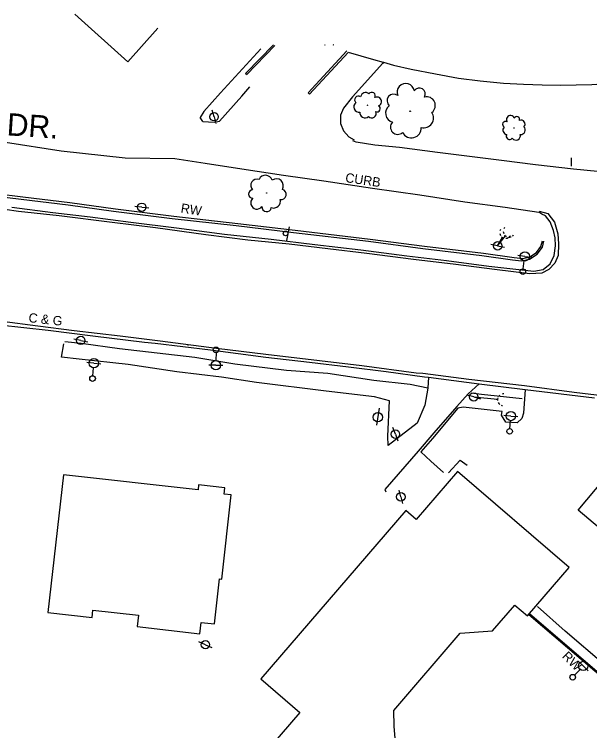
# Model space of a CAD drawing. Extents: x 1722896 to 1754269, y 648279 to 666297.
# Drawn here: x 1726198.2 to 1726506.8, y 658280.2 to 658664.3 of the extents above; entities that cross this region are included whole.
import ezdxf

# ---------------------------------------------------------------- set-up
doc = ezdxf.new("R2010")
doc.units = 0
for name, color, linetype in [('DESIGN - CENTERLINE - Proposed Text', 7, 'Continuous'), ('DESIGN - PUBLIC HEARING - Shapes', 7, 'Continuous'), ('DESIGN - SCRATCH - User 1', 7, 'Continuous'), ('DESIGN - SHEET - Linework', 7, 'Continuous'), ('SURVEY - CENTERLINE - Preliminary Text', 7, 'Continuous'), ('SURVEY - CONTROL with Text', 7, 'Continuous'), ('SURVEY - DTM - Breaklines', 7, 'Continuous'), ('SURVEY - VEGETATION - Features with Text', 7, 'Continuous')]:
    doc.layers.add(name, color=color, linetype=linetype)

msp = doc.modelspace()

# ---------------------------------------------------------------- linework, layer by layer
at = {"layer": 'DESIGN - CENTERLINE - Proposed Text'}
for points in [[(1726230.57, 658664.33), (1726259.14, 658638.87), (1726275.15, 658656.84)], [(1726337.85, 658647.56), (1726322.72, 658631.96), (1726322.33, 658632.71), (1726337.16, 658648.05)], [(1726337.85, 658647.57), (1726337.85, 658647.56)], [(1726364.73, 658647.87), (1726364.79, 658647.92)], [(1726364.79, 658647.92), (1726364.73, 658647.87)], [(1726369.16, 658647.99), (1726369.37, 658647.87)], [(1726369.37, 658647.87), (1726369.31, 658647.93), (1726369.17, 658647.99)], [(1726396.21, 658638.61), (1726401.6, 658637.15), (1726411.07, 658634.99), (1726424.17, 658632.36), (1726436.48, 658630.05), (1726448.04, 658628.66), (1726460.65, 658627.43), (1726471.31, 658626.86), (1726481.34, 658626.43), (1726491.25, 658626.31), (1726507.93, 658626.63), (1726521.3, 658627.67), (1726536.89, 658629.14), (1726548.71, 658630.74), (1726564.84, 658633.77), (1726582.8, 658638.11), (1726595.63, 658641.64), (1726615.41, 658647.76), (1726616.16, 658648.07)], [(1726377.24, 658643.79), (1726356.56, 658621.6), (1726355.76, 658622.3), (1726376.54, 658644.72)], [(1726377.18, 658643.89), (1726377.24, 658643.79)], [(1726377.24, 658644.02), (1726390.77, 658640.08), (1726396.05, 658638.65)], [(1726395.92, 658638.07), (1726379.54, 658620.09), (1726374.67, 658614.04), (1726373.12, 658610.27), (1726373.17, 658605.77), (1726374.74, 658601.83), (1726377.67, 658598.55), (1726380.51, 658597.01), (1726380.55, 658597.11)], [(1726396.19, 658638.37), (1726395.92, 658638.07)], [(1726396.04, 658637.96), (1726396.19, 658638.37)], [(1726496.83, 658587.41), (1726496.94, 658582.94)], [(1726474.26, 658342.49), (1726530.29, 658294.5)], [(1726474.72, 658342.86), (1726530.75, 658294.88)]]:
    msp.add_lwpolyline(points, dxfattribs=at)
for points in [[(1726523.04, 658425.07), (1726583.75, 658373.94), (1726561.29, 658347.28), (1726500.59, 658398.41)], [(1726408.14, 658398.26), (1726330.47, 658307.89), (1726351.36, 658289.94), (1726335.79, 658271.83), (1726356.07, 658254.4), (1726349.83, 658247.15), (1726384.69, 658217.19), (1726388.63, 658221.78), (1726412.46, 658201.3), (1726430.77, 658222.61), (1726390.38, 658257.32), (1726402.8, 658271.77), (1726401.96, 658282.67), (1726401.75, 658290.96), (1726437.26, 658332.38), (1726454.63, 658333.78), (1726466.71, 658347.52), (1726473.45, 658341.72), (1726495.78, 658367.7), (1726435.87, 658419.19), (1726413.75, 658393.44)], [(1726224.49, 658417.45), (1726216.19, 658343.59), (1726239.92, 658340.93), (1726240.36, 658344.81), (1726264.82, 658342.06), (1726264.13, 658335.97), (1726297.75, 658332.19), (1726298.42, 658338.23), (1726305.5, 658337.43), (1726308.22, 658361.65), (1726309.49, 658361.51), (1726314.55, 658406.56), (1726310.74, 658406.99), (1726311.12, 658410.4), (1726297.06, 658411.98), (1726296.77, 658409.34)]]:
    msp.add_lwpolyline(points, close=True, dxfattribs=at)
at = {"layer": 'DESIGN - PUBLIC HEARING - Shapes'}
for p, q in [((1726345.63, 658550.34), (1726344.23, 658542.97)), ((1726392.7, 658444.07), (1726394.03, 658453.1)), ((1726393.16, 658448.26), (1726393.16, 658448.26))]:
    msp.add_line(p, q, dxfattribs=at)
for centre, radius in [((1726343.72, 658546.87), 1.25), ((1726393.17, 658448.28), 2.5)]:
    msp.add_circle(centre, radius, dxfattribs=at)
at = {"layer": 'DESIGN - SCRATCH - User 1'}
for points in [[(1726094.96, 658584.83), (1726116.03, 658578.35), (1726126.54, 658574.84), (1726156.53, 658570.93), (1726187.07, 658566.98), (1726201.87, 658565.19), (1726227.04, 658562.14), (1726251.44, 658558.82), (1726282.92, 658554.87), (1726317.23, 658551.02), (1726347.94, 658547.3), (1726388.24, 658542.61), (1726417.33, 658538.77), (1726448.9, 658535.04), (1726465.48, 658532.74), (1726470.32, 658532.16), (1726474.61, 658533.09), (1726478.63, 658535.74), (1726481.43, 658539.41), (1726482.31, 658542.68)], [(1726096.14, 658585.96), (1726117.24, 658579.48), (1726127.63, 658576.01), (1726157.47, 658572.12), (1726187.99, 658568.17), (1726202.78, 658566.38), (1726227.97, 658563.33), (1726252.37, 658560.01), (1726283.82, 658556.06), (1726318.13, 658552.21), (1726348.84, 658548.5), (1726389.14, 658543.8), (1726418.23, 658539.96), (1726449.8, 658536.23), (1726466.38, 658533.94), (1726470.95, 658533.38), (1726474.72, 658534.21), (1726478.26, 658536.58), (1726480.7, 658539.81), (1726481.5, 658542.79)]]:
    msp.add_lwpolyline(points, dxfattribs=at)
at = {"layer": 'SURVEY - CENTERLINE - Preliminary Text'}
for points in [[(1726330.47, 658645.83), (1726308.71, 658622.18), (1726299.77, 658612.28), (1726297.83, 658609)], [(1726299.3, 658606.94), (1726305.36, 658606.54), (1726308.29, 658607.08), (1726320.14, 658620.52), (1726324.54, 658625.39)], [(1726299.3, 658606.94), (1726297.83, 658609)], [(1726132.12, 658602.07), (1726161.34, 658597.9), (1726193.47, 658595.74), (1726223.25, 658591.16), (1726257.64, 658587.45), (1726284.24, 658586.95)], [(1726440.85, 658588.26), (1726425.11, 658590.26), (1726404.74, 658592.83), (1726391.48, 658594.25), (1726381.56, 658595.78), (1726379.79, 658596.43)], [(1726658.59, 658594.61), (1726655.67, 658591.17), (1726650.24, 658587.65), (1726639.85, 658584.85), (1726626.48, 658582.26), (1726605.57, 658580.12), (1726586.6, 658578.61), (1726566.07, 658577.96), (1726555.1, 658577.83), (1726537.4, 658578.67), (1726518.29, 658579.28), (1726498.14, 658581.3), (1726477.79, 658583.7), (1726459.58, 658585.94), (1726440.85, 658588.26)], [(1726284.24, 658586.95), (1726300.53, 658584.46), (1726320.18, 658581.45), (1726342.56, 658578.13), (1726364.14, 658575.07), (1726390.25, 658571.04), (1726415.77, 658567.51), (1726439.89, 658563.83), (1726461.5, 658560.85), (1726479.59, 658558.3)], [(1726479.78, 658558.79), (1726484.36, 658557.59), (1726487.92, 658552.8), (1726489.82, 658546.63), (1726490.1, 658541.19), (1726489.9, 658534.92), (1726488.19, 658530.86), (1726484.96, 658527.44), (1726481.21, 658525.51), (1726474.67, 658525.2), (1726455.76, 658527.48), (1726435.08, 658530.09), (1726412.37, 658532.84), (1726387.32, 658535.98), (1726366.39, 658538.57), (1726345.58, 658541.09), (1726323.49, 658543.26), (1726300.85, 658546.05), (1726273.87, 658549.75), (1726250.71, 658552.72), (1726222.29, 658556.2), (1726200.43, 658558.54), (1726178.21, 658561.73)], [(1726196.75, 658560.97), (1726218.77, 658558.14), (1726238.82, 658555.72), (1726260.74, 658552.89), (1726285.24, 658549.81), (1726310.96, 658546.46), (1726336.02, 658543.73), (1726359.45, 658540.89), (1726384, 658538.01), (1726408.72, 658534.78), (1726430.05, 658532.24), (1726452.7, 658529.35), (1726468.89, 658527.47), (1726476.79, 658526.67), (1726481.93, 658527.54), (1726485.64, 658530.46), (1726487.69, 658534.92), (1726488.49, 658540.16), (1726488.23, 658544.42), (1726487.39, 658548.45), (1726485.67, 658553.1), (1726483.05, 658556.24), (1726481.08, 658557.1), (1726479.59, 658558.3)], [(1726171.71, 658500.11), (1726189.99, 658497.9), (1726216.26, 658494.91), (1726240.28, 658491.94), (1726267.98, 658488.53), (1726273.76, 658487.92)], [(1726191.6, 658499.71), (1726210.82, 658497.21), (1726230.2, 658494.74), (1726254.9, 658491.93), (1726276.37, 658489.23), (1726306.66, 658485.28), (1726333.07, 658482.01), (1726361.89, 658478.71), (1726384.62, 658475.92), (1726413.82, 658472.11), (1726417.36, 658471.95), (1726441.94, 658468.68), (1726471.88, 658465.31), (1726498.58, 658461.68), (1726514.88, 658459.74)], [(1726419.92, 658463.8), (1726410.61, 658465.78), (1726391.04, 658468.01), (1726366.38, 658471.63), (1726344.17, 658473.39), (1726316.44, 658476.74), (1726295.04, 658480.32), (1726254.64, 658484.92), (1726233.99, 658487.72), (1726225.32, 658488.7)], [(1726273.76, 658487.92), (1726303.35, 658484.33), (1726333.04, 658480.53), (1726356.54, 658477.82), (1726377.37, 658475.26), (1726397.63, 658472.73), (1726418.26, 658469.98), (1726420.34, 658469.71)], [(1726398.75, 658433.19), (1726398.49, 658438.03), (1726399.51, 658457.08), (1726391.33, 658459.18), (1726365.38, 658462.33), (1726328.16, 658466.94), (1726309.25, 658469.71), (1726285.34, 658472.55), (1726259.33, 658476.61), (1726232.99, 658479.35), (1726223.46, 658480.53), (1726224.79, 658487.7)], [(1726291.24, 658486.88), (1726291.17, 658486.82)], [(1726420.34, 658469.71), (1726419.92, 658463.8), (1726418.44, 658454.69), (1726414.21, 658445.08), (1726398.75, 658433.19)], [(1726420.34, 658469.71), (1726447.46, 658466.17), (1726472.28, 658463.15)], [(1726447.46, 658466.17), (1726441.72, 658460.82), (1726435.55, 658454.07)], [(1726472.28, 658463.15), (1726471.4, 658450.45), (1726470.42, 658447.67), (1726467.84, 658445.19), (1726461.89, 658445.62), (1726459.45, 658449.44), (1726459.82, 658451.26), (1726439.03, 658453.71), (1726436.06, 658453.1), (1726422.44, 658436.85), (1726416.21, 658429.66), (1726421.68, 658424.62), (1726428.46, 658418.58)], [(1726470.57, 658458.08), (1726448.87, 658460.47), (1726443.17, 658461.15)], [(1726472.28, 658463.15), (1726509.37, 658458.75)], [(1726435.55, 658454.07), (1726423.16, 658439.87), (1726414.87, 658430.09), (1726396.91, 658409.43), (1726397.42, 658408.21)], [(1726431.15, 658418.39), (1726437.36, 658425.21), (1726441.09, 658422.53)], [(1726546.23, 658306.6), (1726542.46, 658309.64), (1726540.53, 658308.38), (1726533.55, 658299.88), (1726514.62, 658315.72), (1726493.62, 658333.52), (1726478.81, 658346.85)]]:
    msp.add_lwpolyline(points, dxfattribs=at)
at = {"layer": 'SURVEY - DTM - Breaklines'}
for p, q in [((1726305.34, 658609.38), (1726304.38, 658613)), ((1726305.34, 658609.38), (1726306.31, 658605.76)), ((1726266.51, 658560.86), (1726262.77, 658561.19)), ((1726266.51, 658560.86), (1726270.24, 658560.53)), ((1726457.46, 658540.19), (1726461.66, 658545.56)), ((1726461.23, 658545.01), (1726461.66, 658545.56)), ((1726457.46, 658540.19), (1726460.12, 658544.65)), ((1726459.77, 658544.05), (1726460.12, 658544.65)), ((1726457.46, 658540.19), (1726453.76, 658540.85)), ((1726457.46, 658540.19), (1726461.15, 658539.54)), ((1726472.05, 658534.54), (1726468.33, 658535.03)), ((1726472.05, 658534.54), (1726475.77, 658534.05)), ((1726471.17, 658527.85), (1726471.72, 658532.06)), ((1726233.83, 658489.46), (1726230.15, 658490.14)), ((1726233.83, 658489.46), (1726237.52, 658488.78)), ((1726306.37, 658482.91), (1726306.32, 658478.66)), ((1726240.86, 658477.23), (1726237.13, 658477.56)), ((1726240.86, 658477.23), (1726244.6, 658476.9)), ((1726240.27, 658470.51), (1726240.64, 658474.74)), ((1726306.29, 658476.16), (1726302.54, 658476.21)), ((1726306.29, 658476.16), (1726310.04, 658476.11)), ((1726444.62, 658459.15), (1726441, 658460.12)), ((1726444.62, 658459.15), (1726448.25, 658458.17)), ((1726444.62, 658459.15), (1726457.36, 658457.91)), ((1726456.66, 658457.97), (1726457.36, 658457.91)), ((1726464.56, 658448.92), (1726460.83, 658449.23)), ((1726464, 658442.19), (1726464.36, 658446.42)), ((1726464.56, 658448.92), (1726468.3, 658448.61)), ((1726402.6, 658439.19), (1726401.28, 658442.7)), ((1726402.6, 658439.19), (1726403.91, 658435.68)), ((1726405.51, 658405.59), (1726404.54, 658409.21)), ((1726405.51, 658405.59), (1726406.48, 658401.97)), ((1726300.67, 658326.29), (1726297.22, 658327.76)), ((1726300.67, 658326.29), (1726304.12, 658324.81)), ((1726503.35, 658314.87), (1726500.61, 658317.43)), ((1726498.74, 658309.93), (1726501.64, 658313.04)), ((1726503.35, 658314.87), (1726506.09, 658312.31))]:
    msp.add_line(p, q, dxfattribs=at)
for centre, radius in [((1726305.34, 658609.38), 2.25), ((1726266.51, 658560.86), 2.25), ((1726457.46, 658540.19), 2.25), ((1726472.05, 658534.54), 2.5), ((1726470.97, 658526.36), 1.5), ((1726233.83, 658489.46), 2.25), ((1726306.39, 658484.41), 1.5), ((1726240.86, 658477.23), 2.5), ((1726306.29, 658476.16), 2.5), ((1726240.13, 658469.01), 1.5), ((1726444.62, 658459.15), 2.25), ((1726464.56, 658448.92), 2.5), ((1726463.88, 658440.69), 1.5), ((1726402.6, 658439.19), 2.25), ((1726405.51, 658405.59), 2.25), ((1726300.67, 658326.29), 2.25), ((1726503.35, 658314.87), 2.5), ((1726497.72, 658308.84), 1.5)]:
    msp.add_circle(centre, radius, dxfattribs=at)
for centre, major_axis, ratio, start_param, end_param in [((1726463.55, 658548.01), (-2.46, 1.93), 0.999963, 0, 0.255182), ((1726461.69, 658547.33), (-2.68, 1.6), 0.999792, 0.730907, 1.085951), ((1726461.69, 658547.33), (-2.68, 1.6), 0.999792, 0, 0.255182), ((1726463.55, 658548.01), (-2.46, 1.93), 0.999963, 0.730907, 1.085951), ((1726463.55, 658548.01), (-2.46, 1.93), 0.999963, 1.352995, 1.815775), ((1726461.69, 658547.33), (-2.68, 1.6), 0.999792, 2.883049, 3.125465), ((1726463.55, 658548.01), (-2.46, 1.93), 0.999963, 2.883049, 3.125465), ((1726461.69, 658547.33), (-2.68, 1.6), 0.999792, 1.352995, 1.815775), ((1726461.69, 658547.33), (-2.68, 1.6), 0.999792, 2.156577, 2.588895), ((1726463.55, 658548.01), (-2.46, 1.93), 0.999963, 2.156577, 2.588895), ((1726460.45, 658457.63), (0.3, 3.11), 0.999984, 1.352995, 1.815775), ((1726460.45, 658457.63), (0.3, 3.11), 0.999984, 0.730907, 1.085951), ((1726460.45, 658457.63), (0.3, 3.11), 0.999984, 0, 0.255182), ((1726460.45, 658457.63), (0.3, 3.11), 0.999984, 2.156577, 2.588895), ((1726460.45, 658457.63), (0.3, 3.11), 0.999984, 2.883049, 3.125465)]:
    msp.add_ellipse(centre, major_axis=major_axis, ratio=ratio, start_param=start_param, end_param=end_param, dxfattribs=at)
at = {"layer": 'SURVEY - VEGETATION - Features with Text'}
for centre, radius in [((1726387.66, 658615.6), 0.0854), ((1726410.54, 658612.37), 0.163), ((1726466.23, 658603.39), 0.0754), ((1726333.54, 658568.54), 0.116)]:
    msp.add_circle(centre, radius, dxfattribs=at)
for centre, radius, start, end in [((1726408.16, 658622.58), 4.66, 9.1978, 202.6175), ((1726386.54, 658619.77), 2.63, 44.675, 171.5206), ((1726389.97, 658620.6), 1.86, 329.3879, 146.7071), ((1726415.47, 658621.62), 3.21, 329.1771, 147.9227), ((1726382.76, 658618.49), 2.04, 54.8339, 229.8342), ((1726392.79, 658617.54), 2.44, 286.7693, 120.1889), ((1726401.66, 658618), 3.55, 51.8164, 229.1356), ((1726419.35, 658615.44), 4.67, 307.0609, 103.8498), ((1726383.02, 658614.65), 2.77, 124.581, 280.4195), ((1726392.8, 658613.68), 1.68, 246.7486, 65.4942), ((1726402.37, 658611.31), 5.02, 127.1035, 253.9492), ((1726386.29, 658611.62), 2.79, 173.6852, 311.2094), ((1726389.86, 658611.24), 2.45, 224.6324, 21.4213), ((1726417.74, 658608.77), 5.32, 256.1137, 33.6379), ((1726464.34, 658607.86), 2.16, 18.9269, 212.3465), ((1726467.75, 658608), 1.48, 338.9062, 157.6518), ((1726470, 658605.48), 2.16, 316.79, 113.5789), ((1726403.85, 658603.83), 3.9, 137.2624, 312.2627), ((1726411.18, 658603.35), 5.29, 207.0095, 2.848), ((1726461.74, 658605.26), 1.64, 61.5455, 238.8647), ((1726462.58, 658602.27), 2.32, 136.8326, 263.6782), ((1726469.79, 658602.32), 2.46, 265.8428, 43.367), ((1726463.84, 658598.97), 1.8, 146.9915, 321.9918), ((1726467.22, 658599.33), 2.45, 216.7386, 12.5771), ((1726332.94, 658574.24), 3.79, 18.5551, 156.0793), ((1726328.32, 658572.66), 3.33, 69.5023, 226.2913), ((1726338.72, 658572.37), 3.77, 329.4509, 125.2894), ((1726326.09, 658567.97), 2.28, 91.6185, 270.3641), ((1726341.23, 658567.78), 2.78, 259.7038, 74.7041), ((1726328.31, 658563.2), 3.32, 131.6392, 325.0589), ((1726337.3, 658564.03), 3.58, 249.5449, 16.3906), ((1726333.54, 658561.05), 2.53, 174.2578, 351.577)]:
    msp.add_arc(centre, radius, start, end, dxfattribs=at)

# ---------------------------------------------------------------- texts
at = {"layer": 'DESIGN - SCRATCH - User 1'}
for s, rotation, p in [('CURB', 351.7266, (1726375.5, 658574.39)), ('RW', 350.9872, (1726287.21, 658558.07)), ('C & G', 353.7968, (1726205.6, 658499.27))]:
    msp.add_text(s, height=5, rotation=rotation, dxfattribs=at).set_placement(p)
at = {"layer": 'DESIGN - SHEET - Linework'}
msp.add_text('PARK DR.', height=12, rotation=356.1475, dxfattribs=at).set_placement((1726145.82, 658602.7))
at = {"layer": 'SURVEY - CONTROL with Text'}
msp.add_text('RW', height=5, rotation=315.0225, dxfattribs=at).set_placement((1726491.63, 658319.72))

doc.saveas('drawing.dxf')
